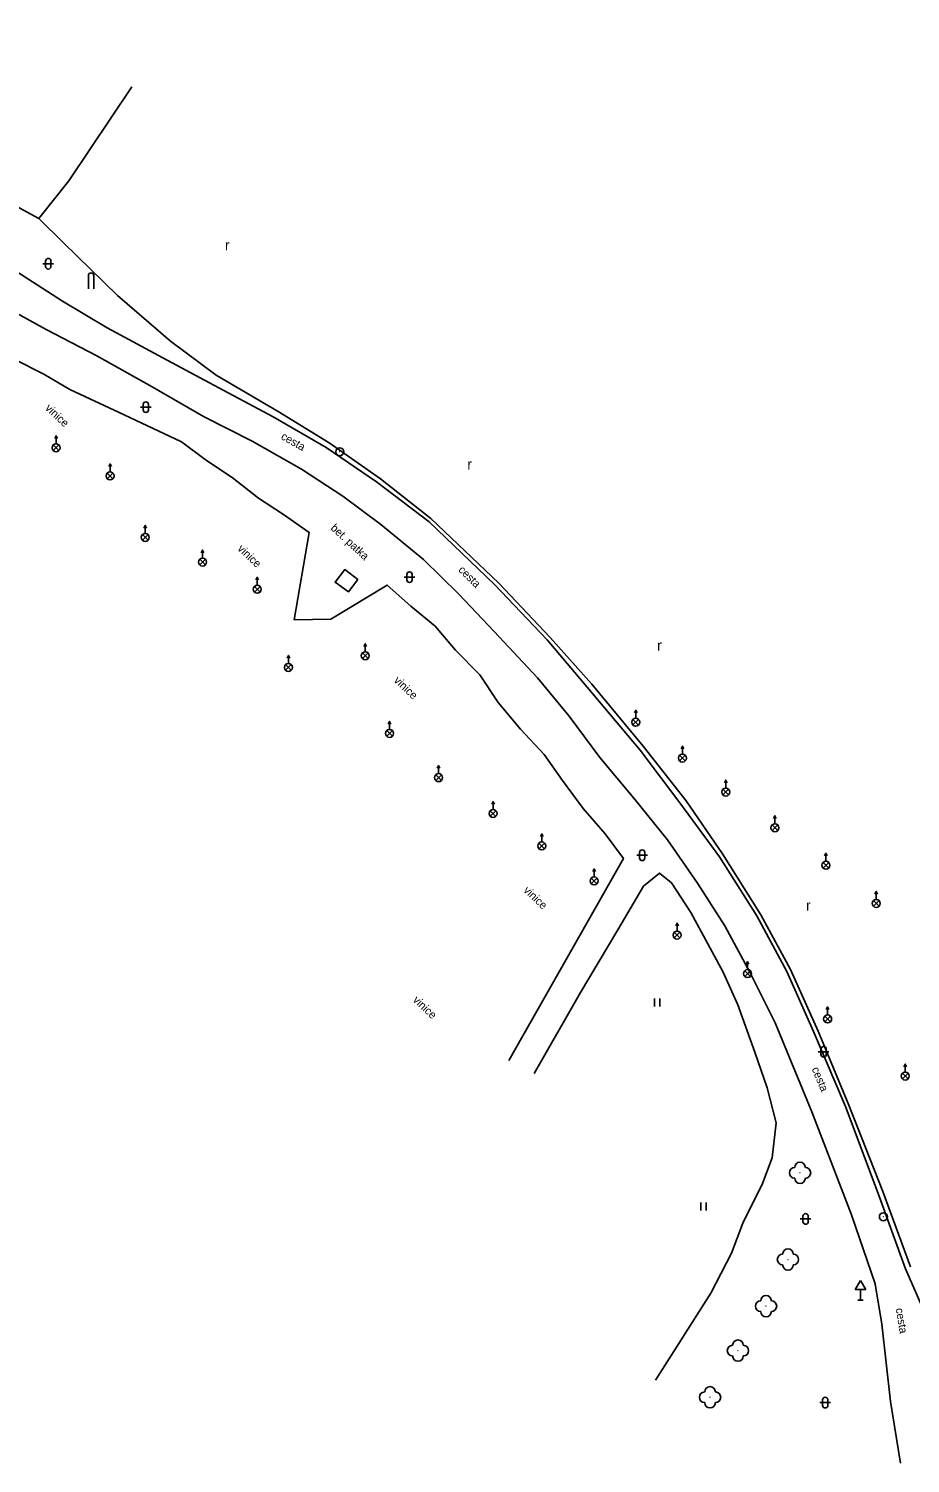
# Model space of a CAD drawing. Extents: x -582188 to -561562, y -1187250 to -1183500.
# Drawn here: x -580545.2 to -580462.6, y -1187147.1 to -1187012.6 of the extents above; entities that cross this region are included whole.
import ezdxf

# ---------------------------------------------------------------- set-up
doc = ezdxf.new("R2010")
doc.units = 0
for name, color, linetype in [('MAP_ZN_BP', 7, 'Continuous'), ('POMOC_POPIS', 7, 'Continuous'), ('ROZHRANÍ_PLOCH', 7, 'Continuous'), ('ZELEŇ', 7, 'Continuous'), ('ZN_BP', 7, 'Continuous'), ('ZN_DOPLŇKOVÉ', 7, 'Continuous'), ('ZN_KULTUR', 7, 'Continuous')]:
    doc.layers.add(name, color=color, linetype=linetype)

msp = doc.modelspace()

# ---------------------------------------------------------------- linework, layer by layer
at = {"layer": 'MAP_ZN_BP'}
for centre, radius in [((-580516.09, -1187052.281), 0.375), ((-580516.09, -1187052.281), 0.0005), ((-580465.13, -1187123.991), 0.375), ((-580465.13, -1187123.991), 0.0005)]:
    msp.add_circle(centre, radius, dxfattribs=at)
at = {"layer": 'ROZHRANÍ_PLOCH'}
for points in [[(-580594.8, -1187011.77), (-580590.43, -1187013.26), (-580585.93, -1187014.76), (-580581.52, -1187016.34), (-580579.94, -1187016.99), (-580578.2, -1187017.49), (-580573.77, -1187019.72), (-580569.4, -1187022.13), (-580566.21, -1187024.03), (-580562.29, -1187026.67), (-580556.57, -1187031.08), (-580552.58, -1187034.75), (-580547.86, -1187038.47), (-580543.6, -1187040.82), (-580538.85, -1187043.3)], [(-580546.3, -1187035.46), (-580542.07, -1187038.18), (-580537.89, -1187040.67), (-580532.27, -1187043.69), (-580527.41, -1187046.28), (-580522.34, -1187049), (-580517.36, -1187051.87), (-580512.65, -1187055.09), (-580507.7, -1187058.84), (-580501.59, -1187064.73), (-580496.64, -1187069.9), (-580492.9, -1187074.35), (-580487.93, -1187080.26), (-580484.13, -1187085.3), (-580480.48, -1187090.26), (-580476.98, -1187095.77), (-580474.17, -1187100.99), (-580471.68, -1187106.61), (-580468.67, -1187113.65), (-580465.62, -1187121.8), (-580463.04, -1187128.86), (-580460.75, -1187134.14)], [(-580538.85, -1187043.3), (-580533.67, -1187046.21), (-580528.86, -1187048.98), (-580524.31, -1187051.28), (-580519.67, -1187053.9), (-580515.8, -1187056.43), (-580512.25, -1187059.11), (-580508.23, -1187062.37), (-580504.92, -1187065.63), (-580501.61, -1187069.13), (-580497.56, -1187073.47), (-580494.58, -1187077.07), (-580491.7, -1187080.93), (-580488.51, -1187084.75), (-580485.38, -1187088.67), (-580482.54, -1187092.72), (-580479.98, -1187096.73), (-580477.62, -1187101.14), (-580475.26, -1187105.82), (-580471.82, -1187114.14), (-580468.1, -1187123.82), (-580465.9, -1187130.28), (-580465.26, -1187134.06), (-580464.47, -1187141.3), (-580463.53, -1187147.1)], [(-580514.38, -1187064.25), (-580515.62, -1187063.32), (-580516.52, -1187064.52), (-580515.28, -1187065.42), (-580514.38, -1187064.25)]]:
    msp.add_lwpolyline(points, dxfattribs=at)
at = {"layer": 'ZELEŇ'}
for points in [[(-580544.31, -1187030.42), (-580541.48, -1187026.88), (-580535.57, -1187018.09)], [(-580550.76, -1187026.92), (-580544.31, -1187030.42), (-580541.98, -1187032.71), (-580536.92, -1187037.65), (-580531.97, -1187041.91), (-580527.66, -1187045.09), (-580521.85, -1187048.5), (-580517.09, -1187051.45), (-580512.27, -1187054.82), (-580507.56, -1187058.53), (-580501.19, -1187064.6), (-580496.36, -1187069.69), (-580492.46, -1187074.07), (-580487.63, -1187079.87), (-580483.6, -1187085), (-580480.22, -1187089.98), (-580476.61, -1187095.69), (-580473.84, -1187100.82), (-580471.25, -1187106.59), (-580468.36, -1187113.52), (-580465.18, -1187121.62), (-580462.58, -1187128.67)], [(-580546.55, -1187043.63), (-580543.82, -1187045), (-580541.4, -1187046.45), (-580536.29, -1187048.82), (-580530.91, -1187051.36), (-580528.59, -1187053.09), (-580526.16, -1187054.71), (-580523.71, -1187056.62), (-580521.36, -1187058.16), (-580518.96, -1187059.84), (-580520.36, -1187068.05), (-580516.94, -1187067.98), (-580511.64, -1187064.78), (-580509.42, -1187066.77), (-580507.14, -1187068.62), (-580505.23, -1187070.87), (-580502.96, -1187073.2), (-580501.24, -1187075.8), (-580499.14, -1187078.27), (-580496.93, -1187080.66), (-580495.2, -1187083.09), (-580493.27, -1187085.72), (-580491.21, -1187088.11), (-580489.49, -1187090.41), (-580500.24, -1187109.33)], [(-580497.86, -1187110.55), (-580493.53, -1187102.97), (-580490.03, -1187097.1), (-580487.62, -1187093), (-580486.11, -1187091.78), (-580485, -1187092.68), (-580483.19, -1187095.47), (-580481.58, -1187098.41), (-580480.15, -1187101.06), (-580478.78, -1187104.14), (-580477.17, -1187108.55), (-580476.02, -1187111.92), (-580475.17, -1187115.2), (-580475.55, -1187118.48), (-580476.47, -1187120.86), (-580478.3, -1187124.58), (-580479.35, -1187127.39), (-580481.3, -1187131.14), (-580486.48, -1187139.31)]]:
    msp.add_lwpolyline(points, dxfattribs=at)
for centre in [(-580472.94, -1187119.87), (-580474.07, -1187128), (-580476.13, -1187132.37), (-580478.76, -1187136.54), (-580481.38, -1187140.91)]:
    msp.add_circle(centre, 0.0005, dxfattribs=at)
for centre, start, end in [((-580473.44, -1187119.87), 89.99999, 269.99999), ((-580472.94, -1187119.37), 0, 179.99999), ((-580472.44, -1187119.87), 270, 89.99999), ((-580472.94, -1187120.37), 179.99999, 359.99999), ((-580474.57, -1187128), 89.99999, 269.99999), ((-580474.07, -1187127.5), 0, 179.99999), ((-580473.57, -1187128), 270, 89.99999), ((-580474.07, -1187128.5), 179.99999, 359.99999), ((-580476.13, -1187131.87), 0, 179.99999), ((-580476.63, -1187132.37), 89.99999, 269.99999), ((-580476.13, -1187132.87), 179.99999, 359.99999), ((-580475.63, -1187132.37), 270, 89.99999), ((-580478.76, -1187136.04), 0, 179.99999), ((-580479.26, -1187136.54), 89.99999, 269.99999), ((-580478.76, -1187137.04), 179.99999, 359.99999), ((-580478.26, -1187136.54), 270, 89.99999), ((-580481.38, -1187140.41), 0, 179.99999), ((-580481.88, -1187140.91), 89.99999, 269.99999), ((-580480.88, -1187140.91), 270, 89.99999), ((-580481.38, -1187141.41), 179.99999, 359.99999)]:
    msp.add_arc(centre, 0.5, start, end, dxfattribs=at)
at = {"layer": 'ZN_BP'}
for p, q in [((-580542.68, -1187051.535), (-580542.68, -1187050.785)), ((-580542.945, -1187052.174), (-580542.416, -1187051.646)), ((-580542.416, -1187052.178), (-580542.945, -1187051.646)), ((-580537.62, -1187054.165), (-580537.62, -1187053.415)), ((-580537.885, -1187054.804), (-580537.356, -1187054.276)), ((-580537.356, -1187054.808), (-580537.885, -1187054.276)), ((-580534.32, -1187059.935), (-580534.32, -1187059.185)), ((-580534.585, -1187060.574), (-580534.056, -1187060.046)), ((-580534.056, -1187060.578), (-580534.585, -1187060.046)), ((-580528.95, -1187062.245), (-580528.95, -1187061.495)), ((-580529.215, -1187062.884), (-580528.686, -1187062.356)), ((-580528.686, -1187062.888), (-580529.215, -1187062.356)), ((-580523.82, -1187064.795), (-580523.82, -1187064.045)), ((-580524.085, -1187065.434), (-580523.556, -1187064.906)), ((-580523.556, -1187065.438), (-580524.085, -1187064.906)), ((-580513.965, -1187071.664), (-580513.436, -1187071.136)), ((-580513.436, -1187071.668), (-580513.965, -1187071.136)), ((-580513.7, -1187071.025), (-580513.7, -1187070.275)), ((-580521.165, -1187072.764), (-580520.636, -1187072.236)), ((-580520.636, -1187072.768), (-580521.165, -1187072.236)), ((-580520.9, -1187072.125), (-580520.9, -1187071.375)), ((-580488.34, -1187077.255), (-580488.34, -1187076.505)), ((-580511.42, -1187078.305), (-580511.42, -1187077.555)), ((-580488.605, -1187077.894), (-580488.076, -1187077.366)), ((-580488.076, -1187077.898), (-580488.605, -1187077.366)), ((-580511.685, -1187078.944), (-580511.156, -1187078.416)), ((-580511.156, -1187078.948), (-580511.685, -1187078.416)), ((-580484.225, -1187081.264), (-580483.696, -1187080.736)), ((-580483.696, -1187081.268), (-580484.225, -1187080.736)), ((-580483.96, -1187080.625), (-580483.96, -1187079.875)), ((-580506.82, -1187082.455), (-580506.82, -1187081.705)), ((-580507.085, -1187083.094), (-580506.556, -1187082.566)), ((-580506.556, -1187083.098), (-580507.085, -1187082.566)), ((-580479.9, -1187083.805), (-580479.9, -1187083.055)), ((-580480.165, -1187084.444), (-580479.636, -1187083.916)), ((-580479.636, -1187084.448), (-580480.165, -1187083.916)), ((-580501.985, -1187086.454), (-580501.456, -1187085.926)), ((-580501.456, -1187086.458), (-580501.985, -1187085.926)), ((-580501.72, -1187085.815), (-580501.72, -1187085.065)), ((-580475.555, -1187087.794), (-580475.026, -1187087.266)), ((-580475.026, -1187087.798), (-580475.555, -1187087.266)), ((-580475.29, -1187087.155), (-580475.29, -1187086.405)), ((-580497.15, -1187088.855), (-580497.15, -1187088.105)), ((-580497.415, -1187089.494), (-580496.886, -1187088.966)), ((-580496.886, -1187089.498), (-580497.415, -1187088.966)), ((-580470.51, -1187090.665), (-580470.51, -1187089.915)), ((-580492.24, -1187092.135), (-580492.24, -1187091.385)), ((-580470.775, -1187091.304), (-580470.246, -1187090.776)), ((-580470.246, -1187091.308), (-580470.775, -1187090.776)), ((-580492.505, -1187092.774), (-580491.976, -1187092.246)), ((-580491.976, -1187092.778), (-580492.505, -1187092.246)), ((-580465.8, -1187094.245), (-580465.8, -1187093.495)), ((-580466.065, -1187094.884), (-580465.536, -1187094.356)), ((-580465.536, -1187094.888), (-580466.065, -1187094.356)), ((-580484.46, -1187097.215), (-580484.46, -1187096.465)), ((-580484.725, -1187097.854), (-580484.196, -1187097.326)), ((-580484.196, -1187097.858), (-580484.725, -1187097.326)), ((-580477.86, -1187100.825), (-580477.86, -1187100.075)), ((-580478.125, -1187101.464), (-580477.596, -1187100.936)), ((-580477.596, -1187101.468), (-580478.125, -1187100.936)), ((-580470.35, -1187105.075), (-580470.35, -1187104.325)), ((-580470.615, -1187105.714), (-580470.086, -1187105.186)), ((-580470.086, -1187105.718), (-580470.615, -1187105.186)), ((-580463.08, -1187110.425), (-580463.08, -1187109.675)), ((-580463.345, -1187111.064), (-580462.816, -1187110.536)), ((-580462.816, -1187111.068), (-580463.345, -1187110.536))]:
    msp.add_line(p, q, dxfattribs=at)
for points in [[(-580542.805, -1187051.035), (-580542.68, -1187050.785), (-580542.555, -1187051.035)], [(-580537.745, -1187053.665), (-580537.62, -1187053.415), (-580537.495, -1187053.665)], [(-580534.445, -1187059.435), (-580534.32, -1187059.185), (-580534.195, -1187059.435)], [(-580529.075, -1187061.745), (-580528.95, -1187061.495), (-580528.825, -1187061.745)], [(-580523.945, -1187064.295), (-580523.82, -1187064.045), (-580523.695, -1187064.295)], [(-580513.825, -1187070.525), (-580513.7, -1187070.275), (-580513.575, -1187070.525)], [(-580521.025, -1187071.625), (-580520.9, -1187071.375), (-580520.775, -1187071.625)], [(-580488.465, -1187076.755), (-580488.34, -1187076.505), (-580488.215, -1187076.755)], [(-580511.545, -1187077.805), (-580511.42, -1187077.555), (-580511.295, -1187077.805)], [(-580484.085, -1187080.125), (-580483.96, -1187079.875), (-580483.835, -1187080.125)], [(-580506.945, -1187081.955), (-580506.82, -1187081.705), (-580506.695, -1187081.955)], [(-580480.025, -1187083.305), (-580479.9, -1187083.055), (-580479.775, -1187083.305)], [(-580501.845, -1187085.315), (-580501.72, -1187085.065), (-580501.595, -1187085.315)], [(-580475.415, -1187086.655), (-580475.29, -1187086.405), (-580475.165, -1187086.655)], [(-580497.275, -1187088.355), (-580497.15, -1187088.105), (-580497.025, -1187088.355)], [(-580470.635, -1187090.165), (-580470.51, -1187089.915), (-580470.385, -1187090.165)], [(-580492.365, -1187091.635), (-580492.24, -1187091.385), (-580492.115, -1187091.635)], [(-580465.925, -1187093.745), (-580465.8, -1187093.495), (-580465.675, -1187093.745)], [(-580484.585, -1187096.715), (-580484.46, -1187096.465), (-580484.335, -1187096.715)], [(-580477.985, -1187100.325), (-580477.86, -1187100.075), (-580477.735, -1187100.325)], [(-580470.475, -1187104.575), (-580470.35, -1187104.325), (-580470.225, -1187104.575)], [(-580463.205, -1187109.925), (-580463.08, -1187109.675), (-580462.955, -1187109.925)]]:
    msp.add_lwpolyline(points, dxfattribs=at)
for centre in [(-580542.68, -1187051.91), (-580537.62, -1187054.54), (-580534.32, -1187060.31), (-580528.95, -1187062.62), (-580523.82, -1187065.17), (-580513.7, -1187071.4), (-580520.9, -1187072.5), (-580488.34, -1187077.63), (-580511.42, -1187078.68), (-580483.96, -1187081), (-580506.82, -1187082.83), (-580479.9, -1187084.18), (-580501.72, -1187086.19), (-580475.29, -1187087.53), (-580497.15, -1187089.23), (-580470.51, -1187091.04), (-580492.24, -1187092.51), (-580465.8, -1187094.62), (-580484.46, -1187097.59), (-580477.86, -1187101.2), (-580470.35, -1187105.45), (-580463.08, -1187110.8)]:
    msp.add_circle(centre, 0.375, dxfattribs=at)
at = {"layer": 'ZN_DOPLŇKOVÉ'}
for p, q in [((-580539.65, -1187037.01), (-580539.65, -1187035.76)), ((-580539.15, -1187037.01), (-580539.15, -1187035.76)), ((-580467.27, -1187129.954), (-580467.77, -1187130.82)), ((-580467.27, -1187129.954), (-580466.77, -1187130.82)), ((-580467.77, -1187130.82), (-580466.77, -1187130.82)), ((-580467.52, -1187131.82), (-580467.02, -1187131.82)), ((-580467.27, -1187131.82), (-580467.27, -1187130.82))]:
    msp.add_line(p, q, dxfattribs=at)
msp.add_arc((-580539.4, -1187035.76), 0.25, 0, 179.99999, dxfattribs=at)
at = {"layer": 'ZN_KULTUR'}
for p, q in [((-580543.91, -1187034.66), (-580542.91, -1187034.66)), ((-580543.66, -1187034.91), (-580543.66, -1187034.41)), ((-580543.16, -1187034.91), (-580543.16, -1187034.41)), ((-580534.77, -1187048.1), (-580533.77, -1187048.1)), ((-580534.52, -1187048.35), (-580534.52, -1187047.85)), ((-580534.02, -1187048.35), (-580534.02, -1187047.85)), ((-580510.05, -1187064.04), (-580509.05, -1187064.04)), ((-580509.8, -1187064.29), (-580509.8, -1187063.79)), ((-580509.3, -1187064.29), (-580509.3, -1187063.79)), ((-580488.24, -1187090.1), (-580487.24, -1187090.1)), ((-580487.99, -1187090.35), (-580487.99, -1187089.85)), ((-580487.49, -1187090.35), (-580487.49, -1187089.85)), ((-580486.59, -1187104.285), (-580486.59, -1187103.535)), ((-580486.09, -1187104.285), (-580486.09, -1187103.535)), ((-580471.23, -1187108.53), (-580470.23, -1187108.53)), ((-580470.98, -1187108.78), (-580470.98, -1187108.28)), ((-580470.48, -1187108.78), (-580470.48, -1187108.28)), ((-580482.25, -1187123.405), (-580482.25, -1187122.655)), ((-580481.75, -1187123.405), (-580481.75, -1187122.655)), ((-580472.92, -1187124.19), (-580471.92, -1187124.19)), ((-580472.67, -1187124.44), (-580472.67, -1187123.94)), ((-580472.17, -1187124.44), (-580472.17, -1187123.94)), ((-580470.83, -1187141.66), (-580470.83, -1187141.16)), ((-580470.33, -1187141.66), (-580470.33, -1187141.16)), ((-580471.08, -1187141.41), (-580470.08, -1187141.41))]:
    msp.add_line(p, q, dxfattribs=at)
for centre, start, end in [((-580543.41, -1187034.41), 0, 179.99999), ((-580543.41, -1187034.91), 179.99999, 359.99999), ((-580534.27, -1187047.85), 0, 179.99999), ((-580534.27, -1187048.35), 179.99999, 359.99999), ((-580509.55, -1187063.79), 0, 179.99999), ((-580509.55, -1187064.29), 179.99999, 359.99999), ((-580487.74, -1187089.85), 0, 179.99999), ((-580487.74, -1187090.35), 179.99999, 359.99999), ((-580470.73, -1187108.28), 0, 179.99999), ((-580470.73, -1187108.78), 179.99999, 359.99999), ((-580472.42, -1187123.94), 0, 179.99999), ((-580472.42, -1187124.44), 179.99999, 359.99999), ((-580470.58, -1187141.16), 0, 179.99999), ((-580470.58, -1187141.66), 179.99999, 359.99999)]:
    msp.add_arc(centre, 0.25, start, end, dxfattribs=at)

# ---------------------------------------------------------------- texts
at = {"layer": 'POMOC_POPIS'}
for s, rotation, p in [('cesta', 330.54853, (-580521.67, -1187051.05)), ('bet. patka', 317.33982, (-580517.01, -1187059.51)), ('cesta', 315.43603, (-580505.03, -1187063.42)), ('cesta', 292.46321, (-580471.86, -1187110.12)), ('cesta', 279.60974, (-580463.98, -1187132.61))]:
    msp.add_text(s, height=0.75, rotation=rotation, dxfattribs=at).set_placement(p)
at = {"layer": 'ZELEŇ'}
for p in [(-580543.76, -1187048.26), (-580525.73, -1187061.44), (-580511.07, -1187073.78), (-580498.92, -1187093.46), (-580509.29, -1187103.74)]:
    msp.add_text('vinice', height=0.75, rotation=316.44413, dxfattribs=at).set_placement(p)
at = {"layer": 'ZN_KULTUR'}
for p in [(-580526.858, -1187033.412), (-580504.138, -1187053.952), (-580486.348, -1187070.932), (-580472.388, -1187095.302)]:
    msp.add_text('r', height=1, dxfattribs=at).set_placement(p)

doc.saveas('drawing.dxf')
